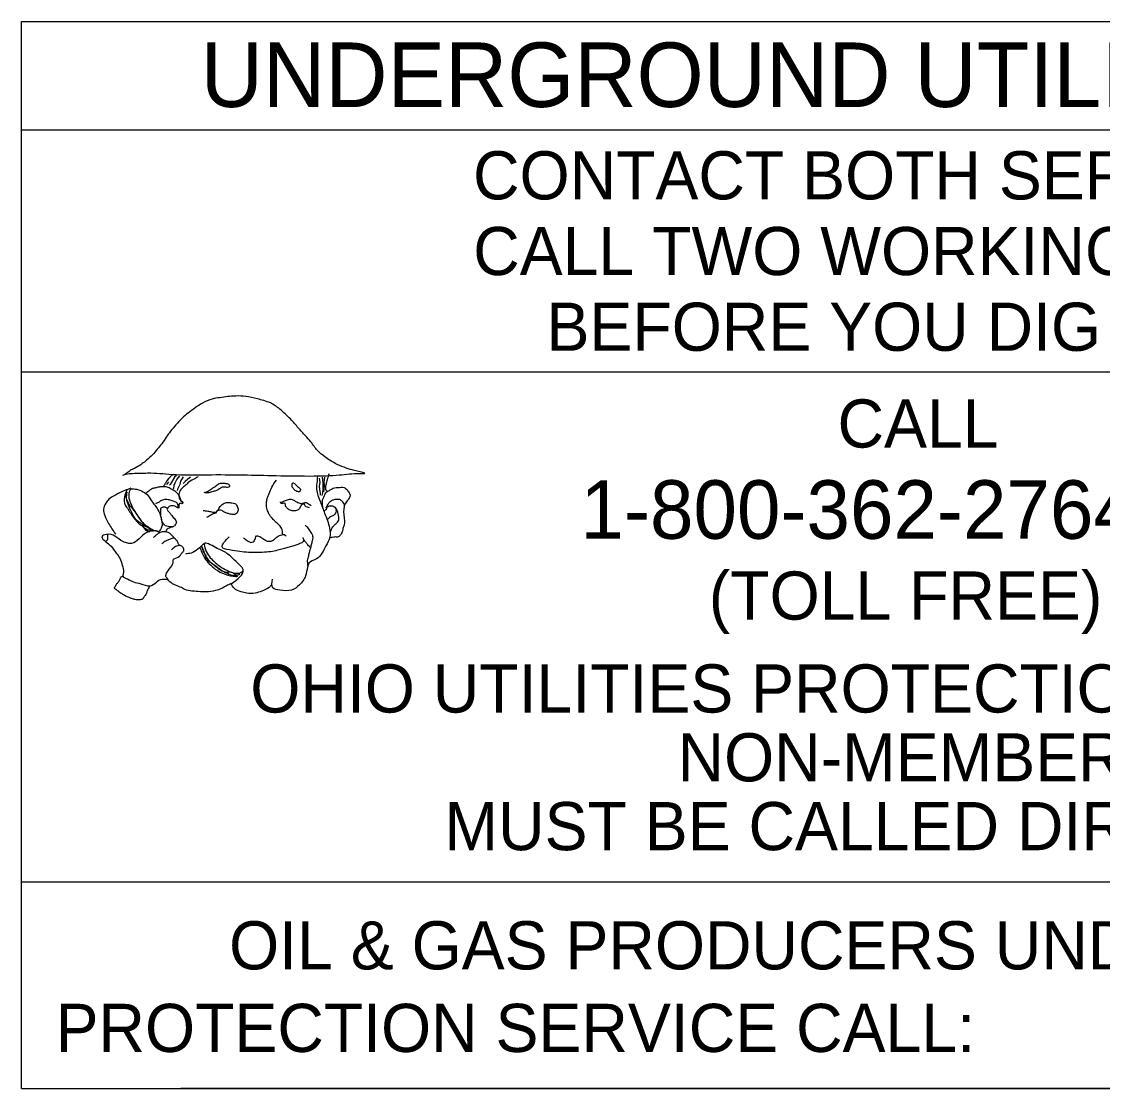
# Model space of a CAD drawing. Extents: x 0.4 to 34.4, y -2.1 to 19.9.
# Drawn here: x 3.425 to 6.568, y 0.086 to 3.186 of the extents above; entities that cross this region are included whole.
import ezdxf

# ---------------------------------------------------------------- set-up
doc = ezdxf.new("R2010")
doc.units = 0
doc.layers.add('SH_Data', color=7, linetype='Continuous')

msp = doc.modelspace()

# ---------------------------------------------------------------- linework, layer by layer
at = {"layer": 'SH_Data'}
for p, q in [((3.4251, 3.186), (8.6251, 3.186)), ((3.4251, 0.086), (3.4251, 3.186)), ((8.6251, 2.8706), (3.4251, 2.8706)), ((3.4251, 2.1681), (8.6251, 2.1681)), ((3.8694, 1.8617), (3.8624, 1.8509)), ((3.8752, 1.8667), (3.8694, 1.8617)), ((3.8762, 1.8559), (3.8703, 1.845)), ((3.8841, 1.8656), (3.8762, 1.8559)), ((3.895, 1.8627), (3.8871, 1.8509)), ((3.9087, 1.8559), (3.9008, 1.85)), ((3.9166, 1.8617), (3.9087, 1.8559)), ((4.2903, 1.8597), (4.2923, 1.8469)), ((4.2991, 1.8617), (4.3011, 1.846)), ((4.3061, 1.8617), (4.3041, 1.848)), ((3.8526, 1.8489), (3.8466, 1.8411)), ((3.8466, 1.8411), (3.8466, 1.8411)), ((3.8566, 1.8411), (3.8555, 1.8391)), ((3.8624, 1.8509), (3.8566, 1.8411)), ((3.8674, 1.8381), (3.8663, 1.8292)), ((3.8663, 1.8292), (3.8674, 1.8283)), ((3.8703, 1.845), (3.8674, 1.8381)), ((3.8782, 1.8272), (3.8771, 1.8233)), ((3.8811, 1.8331), (3.8782, 1.8272)), ((3.8851, 1.8411), (3.8811, 1.8331)), ((3.8871, 1.8509), (3.8851, 1.8411)), ((3.9008, 1.85), (3.895, 1.844)), ((4.2923, 1.8469), (4.2903, 1.8361)), ((4.2903, 1.8361), (4.2912, 1.8272)), ((4.2912, 1.8272), (4.2932, 1.8144)), ((4.3011, 1.8263), (4.3002, 1.8164)), ((4.3011, 1.846), (4.3011, 1.8351)), ((4.3011, 1.8351), (4.3011, 1.8263)), ((4.3041, 1.8263), (4.3031, 1.8193)), ((4.3041, 1.848), (4.3051, 1.8391)), ((4.3051, 1.8391), (4.3041, 1.8263)), ((4.2932, 1.8144), (4.2932, 1.8096)), ((4.3002, 1.8164), (4.2982, 1.8085)), ((3.4251, 0.686), (8.6251, 0.686)), ((3.4251, 0.086), (8.6251, 0.086)), ((3.8882, 0.086), (8.1621, 0.086)), ((8.1621, 0.086), (3.8882, 0.086))]:
    msp.add_line(p, q, dxfattribs=at)
for points in [[(4.42, 1.8727), (4.4223, 1.873), (4.4011, 1.8798), (4.3863, 1.8831), (4.3627, 1.8908), (4.3367, 1.9022), (4.3063, 1.9215), (4.2854, 1.9394), (4.2662, 1.9648), (4.2502, 1.9825), (4.2296, 2.0056), (4.2067, 2.0312), (4.1758, 2.0598), (4.1483, 2.0777), (4.1105, 2.0897), (4.0766, 2.0967), (4.0475, 2.098), (4.0011, 2.0931), (3.9795, 2.0891), (3.9513, 2.0776), (3.9295, 2.0635), (3.9095, 2.0484), (3.8916, 2.0335), (3.8736, 2.0144), (3.8579, 1.9954), (3.8457, 1.9783), (3.8324, 1.9594), (3.8196, 1.9435), (3.8059, 1.9271), (3.7881, 1.9112), (3.7758, 1.9014), (3.7583, 1.8902), (3.748, 1.8852), (3.7466, 1.8846), (3.7353, 1.8771), (3.7309, 1.8743), (3.7251, 1.8698)], [(3.7192, 1.868), (3.7251, 1.8698), (3.7416, 1.8729), (3.7659, 1.8733), (3.7916, 1.8743), (3.862, 1.8702), (3.9648, 1.8693), (4.0696, 1.8688), (4.165, 1.8668), (4.2755, 1.8656), (4.3486, 1.8686), (4.4075, 1.8731), (4.42, 1.8727)], [(3.8665, 1.8708), (3.8646, 1.8691), (3.8621, 1.8676), (3.858, 1.864), (3.8526, 1.8579), (3.8486, 1.8522), (3.8451, 1.8481), (3.8432, 1.8452), (3.8392, 1.8381), (3.8386, 1.8368), (3.8379, 1.8356), (3.8291, 1.8338), (3.825, 1.8335), (3.8166, 1.8316), (3.8078, 1.8296), (3.803, 1.8277), (3.7957, 1.8226), (3.7917, 1.8198), (3.7862, 1.8151)], [(3.9386, 1.8639), (3.9288, 1.8577), (3.9113, 1.8476), (3.9011, 1.8379), (3.8906, 1.8292), (3.8831, 1.816), (3.8825, 1.8079), (3.8874, 1.7956), (3.8937, 1.7877), (3.8912, 1.785), (3.8846, 1.7859), (3.8821, 1.778), (3.8819, 1.7726), (3.8704, 1.7783), (3.8641, 1.7789), (3.8541, 1.7771), (3.8488, 1.7683), (3.8541, 1.7606), (3.8604, 1.753), (3.8683, 1.7426), (3.8755, 1.7306), (3.8698, 1.7208)], [(4.2851, 1.8639), (4.2841, 1.851), (4.2827, 1.8276), (4.2938, 1.7897), (4.3061, 1.7576), (4.3204, 1.7138), (4.3211, 1.6876), (4.3098, 1.6622), (4.2824, 1.6246), (4.2604, 1.6118), (4.2562, 1.6002), (4.2507, 1.5756), (4.233, 1.5491), (4.2101, 1.534), (4.1758, 1.5342), (4.1558, 1.5405), (4.1548, 1.5656)], [(4.3191, 1.871), (4.3188, 1.8705), (4.3163, 1.8646), (4.3161, 1.8629), (4.3132, 1.8547), (4.3117, 1.848), (4.3104, 1.8415), (4.3083, 1.8319), (4.3084, 1.8291), (4.3091, 1.8256), (4.3115, 1.8231), (4.3129, 1.8204)], [(3.7426, 1.8301), (3.7075, 1.8152), (3.6944, 1.8081), (3.6791, 1.7983), (3.6696, 1.7862), (3.6632, 1.769), (3.6669, 1.7506), (3.6782, 1.7279), (3.6978, 1.6962)], [(3.7305, 1.8242), (3.7242, 1.8047), (3.7261, 1.7808), (3.7302, 1.7751), (3.7391, 1.7616), (3.7482, 1.7483), (3.7595, 1.7344), (3.7699, 1.7247), (3.7792, 1.7176), (3.7856, 1.7086), (3.797, 1.7035)], [(3.7312, 1.8252), (3.7287, 1.8186), (3.7278, 1.8104), (3.7282, 1.8047), (3.7313, 1.7963), (3.7362, 1.785), (3.7446, 1.7739), (3.7573, 1.7572), (3.7648, 1.7462), (3.7731, 1.7355), (3.7825, 1.7252), (3.7948, 1.7146), (3.7758, 1.7225), (3.789, 1.7109), (3.8004, 1.7083), (3.7646, 1.7326), (3.7486, 1.7534), (3.7409, 1.7692), (3.7345, 1.7833), (3.7305, 1.8005), (3.7317, 1.8183)], [(3.7426, 1.8277), (3.7394, 1.823), (3.7366, 1.8064), (3.7415, 1.7872), (3.7546, 1.7621), (3.7663, 1.7446), (3.7813, 1.7258), (3.7917, 1.7185), (3.8021, 1.7116), (3.8155, 1.7062), (3.8255, 1.7031)], [(3.7441, 1.8286), (3.76, 1.8268), (3.7781, 1.82), (3.793, 1.8081), (3.8054, 1.7891), (3.8145, 1.7777), (3.8266, 1.7563), (3.8323, 1.7381), (3.8323, 1.7168), (3.8244, 1.7044)], [(3.8927, 1.7881), (3.8911, 1.7906), (3.8878, 1.7971), (3.8842, 1.8067), (3.8776, 1.8158), (3.8705, 1.8217), (3.8604, 1.8275), (3.8482, 1.8334), (3.835, 1.8343)], [(3.9545, 1.819), (3.9611, 1.8172), (3.9732, 1.8186), (3.9857, 1.8221), (3.9948, 1.8255), (4.0058, 1.8322), (4.0131, 1.8344), (4.0234, 1.8333), (4.0307, 1.8355), (4.0277, 1.8411), (4.0203, 1.8431), (4.0096, 1.8438), (4.0027, 1.8435), (3.9911, 1.8365), (3.9837, 1.8318), (3.9709, 1.8231), (3.9655, 1.8196), (3.9571, 1.8171)], [(4.1852, 1.6954), (4.1841, 1.6973), (4.1841, 1.7016), (4.1836, 1.7052), (4.1805, 1.7143), (4.1727, 1.7239), (4.1633, 1.7326), (4.157, 1.7392), (4.1465, 1.7514), (4.1416, 1.761), (4.1376, 1.7762), (4.1374, 1.7909), (4.1395, 1.8016), (4.1452, 1.8148), (4.1526, 1.8331), (4.1663, 1.8533)], [(4.2132, 1.8437), (4.2111, 1.8423), (4.2107, 1.8396), (4.2107, 1.8352), (4.213, 1.8319), (4.2191, 1.8248), (4.2253, 1.8219), (4.2331, 1.8202), (4.2363, 1.8239), (4.2366, 1.8264), (4.2333, 1.8304), (4.2277, 1.8346), (4.2211, 1.8412), (4.2132, 1.8451)], [(4.3011, 1.7727), (4.3011, 1.7746), (4.3003, 1.7793), (4.2998, 1.7863), (4.2994, 1.7914), (4.3019, 1.8004), (4.3051, 1.8071), (4.3082, 1.8142), (4.3116, 1.8184), (4.3203, 1.8237), (4.3276, 1.8287), (4.3352, 1.8312), (4.3448, 1.8321), (4.354, 1.8327), (4.3625, 1.8319), (4.3673, 1.8291), (4.3725, 1.8242), (4.3755, 1.8194), (4.3794, 1.813), (4.3795, 1.8059), (4.377, 1.8), (4.3733, 1.7952), (4.3694, 1.7906), (4.3661, 1.7848), (4.364, 1.7804), (4.3626, 1.7744), (4.3616, 1.7673), (4.3613, 1.7592), (4.3621, 1.7508), (4.3634, 1.7414), (4.364, 1.7326), (4.3633, 1.7248), (4.3601, 1.7158), (4.3591, 1.7101), (4.3574, 1.7029), (4.3545, 1.6979), (4.3516, 1.6933), (4.3495, 1.6905), (4.3436, 1.688), (4.3374, 1.6883), (4.3326, 1.6876), (4.3241, 1.6872), (4.3211, 1.6871)], [(3.8807, 1.7756), (3.8799, 1.7796), (3.8754, 1.7884), (3.8661, 1.7921), (3.8542, 1.7959), (3.8406, 1.7968), (3.829, 1.7931), (3.8246, 1.7896), (3.8166, 1.786), (3.8151, 1.7851)], [(4.1769, 1.7879), (4.1834, 1.7909), (4.1921, 1.7946), (4.2036, 1.7981), (4.2142, 1.7967), (4.2228, 1.7915), (4.2284, 1.7887), (4.2391, 1.7858), (4.2523, 1.7888), (4.2567, 1.7863), (4.2623, 1.7831), (4.2667, 1.7801)], [(4.3103, 1.7733), (4.3117, 1.7752), (4.3136, 1.7786), (4.3165, 1.7842), (4.3196, 1.7888), (4.3248, 1.7933), (4.3284, 1.7955), (4.3321, 1.7963), (4.3361, 1.798), (4.3409, 1.7985), (4.3471, 1.7981), (4.3512, 1.7973), (4.3541, 1.7947), (4.3579, 1.7916), (4.3609, 1.786), (4.3625, 1.7843), (4.3628, 1.7823), (4.3632, 1.7796)], [(3.8411, 1.7218), (3.8376, 1.7269), (3.8336, 1.7323), (3.8319, 1.7411), (3.8296, 1.7489), (3.8295, 1.7546), (3.8296, 1.7659), (3.8325, 1.7743), (3.8369, 1.7756), (3.8413, 1.7756), (3.845, 1.7742), (3.8491, 1.7719), (3.8502, 1.77)], [(3.964, 1.7456), (3.9673, 1.7476), (3.9738, 1.7515), (3.98, 1.7556), (3.9874, 1.758), (3.9913, 1.759), (3.9903, 1.759), (3.9781, 1.7605), (3.9663, 1.7626), (3.9534, 1.7648)], [(3.9881, 1.758), (3.9967, 1.7675), (4.0007, 1.7742), (4.0112, 1.7846), (4.0241, 1.789), (4.0366, 1.7872), (4.0451, 1.7861), (4.0515, 1.7779), (4.0546, 1.766), (4.0532, 1.7612), (4.0496, 1.7562), (4.0437, 1.7539), (4.0308, 1.7551), (4.022, 1.7575), (4.0153, 1.7602), (4.0071, 1.7656)], [(4.0056, 1.766), (3.9983, 1.7663), (3.9969, 1.7655), (3.9932, 1.7621)], [(4.1828, 1.7856), (4.1787, 1.7871), (4.1783, 1.7901)], [(4.2479, 1.7881), (4.2436, 1.7841), (4.2391, 1.7808), (4.2359, 1.7768), (4.2327, 1.7706), (4.2295, 1.7672), (4.2242, 1.7654), (4.2181, 1.7642), (4.2062, 1.7663), (4.2, 1.7688), (4.1962, 1.7729), (4.1924, 1.7805), (4.1916, 1.7858), (4.1876, 1.7864), (4.1824, 1.7851)], [(4.2446, 1.7877), (4.2487, 1.7796), (4.2554, 1.7756), (4.2611, 1.7739)], [(4.3053, 1.7629), (4.3065, 1.7651), (4.3111, 1.7685), (4.3129, 1.7736), (4.3161, 1.7772), (4.3238, 1.7791), (4.3298, 1.7786), (4.3357, 1.7746), (4.3399, 1.7694), (4.3402, 1.7689), (4.3399, 1.7646), (4.3388, 1.76), (4.3361, 1.7548), (4.332, 1.7509), (4.3273, 1.7484), (4.3229, 1.7465), (4.3188, 1.7429), (4.3149, 1.7389)], [(4.3242, 1.7047), (4.3259, 1.7115), (4.3278, 1.7151), (4.3321, 1.72), (4.335, 1.7236), (4.3394, 1.7272), (4.3437, 1.7317), (4.347, 1.7371), (4.3475, 1.7469), (4.3452, 1.7565), (4.3428, 1.765), (4.3387, 1.7669)], [(3.824, 1.7033), (3.8162, 1.7059), (3.8066, 1.7056), (3.7871, 1.7005), (3.745, 1.6696), (3.7342, 1.6701), (3.7199, 1.6748), (3.6965, 1.6908), (3.6717, 1.6958), (3.6586, 1.689), (3.6687, 1.6755), (3.6855, 1.6613), (3.6998, 1.6417), (3.7106, 1.6265), (3.7176, 1.6064), (3.7212, 1.5852), (3.7199, 1.5748), (3.7332, 1.5663), (3.75, 1.5581), (3.7713, 1.5526), (3.7976, 1.5462), (3.817, 1.5571), (3.8341, 1.566), (3.8503, 1.5665), (3.8446, 1.5733), (3.8446, 1.5764), (3.8586, 1.6006), (3.8657, 1.6183), (3.8653, 1.62), (3.8806, 1.6297), (3.8916, 1.6426), (3.8966, 1.6485), (3.8946, 1.6579), (3.8861, 1.6633), (3.8721, 1.6602), (3.8612, 1.651)], [(3.8688, 1.6847), (3.8673, 1.6876), (3.8616, 1.6933), (3.855, 1.6997), (3.8465, 1.7023), (3.8376, 1.7033), (3.8306, 1.7019), (3.8219, 1.6983), (3.8146, 1.6923), (3.8084, 1.6865)], [(3.8691, 1.72), (3.8669, 1.7189), (3.8591, 1.7181), (3.8513, 1.7187), (3.8429, 1.7204)], [(3.868, 1.7188), (3.8624, 1.7173), (3.8582, 1.7162), (3.8541, 1.7143), (3.8488, 1.7113), (3.8466, 1.7094), (3.8455, 1.7076), (3.844, 1.7022)], [(4.2557, 1.6051), (4.2569, 1.6085), (4.2566, 1.6158), (4.2591, 1.631), (4.2621, 1.6429), (4.2667, 1.6606), (4.2695, 1.6726), (4.2723, 1.6831), (4.2721, 1.6901), (4.2711, 1.695), (4.2671, 1.7017), (4.2594, 1.713), (4.2492, 1.7226)], [(3.6683, 1.676), (3.6746, 1.6796), (3.6762, 1.6869), (3.6754, 1.6955)], [(3.8846, 1.6633), (3.8816, 1.6676), (3.8781, 1.6751), (3.8733, 1.6811), (3.8688, 1.6847), (3.8644, 1.6847), (3.8549, 1.6812), (3.845, 1.6767), (3.8333, 1.6686)], [(3.9552, 1.6696), (3.9177, 1.6414), (3.9023, 1.6392)], [(4.0341, 1.5521), (4.069, 1.5929), (4.0476, 1.6179), (4.0219, 1.6408), (3.9888, 1.6579), (3.9566, 1.6685), (3.9595, 1.6518), (3.984, 1.6176), (4.0233, 1.5909), (4.0667, 1.5884), (4.0682, 1.5901)], [(4.2646, 1.6569), (4.2623, 1.6602), (4.2571, 1.6651), (4.2511, 1.6733), (4.2484, 1.6764), (4.2462, 1.679), (4.2448, 1.6771), (4.2401, 1.6717), (4.228, 1.6669), (4.2162, 1.6626), (4.2031, 1.6584), (4.1891, 1.6551), (4.1737, 1.6509), (4.155, 1.6465), (4.1316, 1.6438), (4.104, 1.6431), (4.0851, 1.6433), (4.0596, 1.6459), (4.0295, 1.6506), (4.0079, 1.6601), (4.0126, 1.671), (4.0286, 1.6892)], [(4.0705, 1.6854), (4.0727, 1.6842), (4.0783, 1.6801), (4.0842, 1.676), (4.0913, 1.6726), (4.0986, 1.6744), (4.1027, 1.6787), (4.1048, 1.6848), (4.108, 1.6913), (4.1138, 1.691), (4.1265, 1.6841), (4.1376, 1.6773), (4.1469, 1.6759), (4.1607, 1.6821), (4.1684, 1.6887), (4.182, 1.6946), (4.189, 1.6951), (4.1941, 1.6919)], [(4.2459, 1.6793), (4.2459, 1.6813), (4.244, 1.6843), (4.244, 1.6872)], [(3.9428, 1.6584), (3.9569, 1.6281), (3.9883, 1.5951), (4.0479, 1.5739), (4.0536, 1.574)], [(3.9476, 1.6612), (3.9536, 1.6493), (3.9662, 1.6214), (3.9852, 1.6075), (4.0023, 1.5944), (4.0241, 1.5827), (4.0437, 1.5764), (4.0577, 1.5794)], [(3.9495, 1.6581), (3.9533, 1.6456), (3.9571, 1.6409), (3.9612, 1.633), (3.9658, 1.6247), (3.9751, 1.614), (3.9852, 1.6063), (3.9994, 1.5952), (4.0098, 1.589), (4.023, 1.5861), (4.0378, 1.5855), (4.0471, 1.5787), (4.0574, 1.5794), (4.0592, 1.5804)], [(3.7976, 1.5466), (3.7957, 1.5426), (3.7921, 1.5358), (3.7892, 1.5289), (3.7863, 1.5215), (3.7828, 1.5161), (3.7799, 1.5121), (3.7765, 1.5076), (3.7725, 1.5062), (3.7626, 1.5056), (3.7542, 1.5067), (3.7459, 1.5092), (3.7375, 1.5121), (3.7316, 1.5141), (3.7261, 1.5171), (3.7198, 1.5215), (3.7148, 1.5244), (3.7094, 1.5284), (3.7065, 1.5304), (3.7011, 1.5343), (3.698, 1.5368), (3.6946, 1.5392), (3.6966, 1.5431), (3.7011, 1.5511), (3.7065, 1.5576), (3.7109, 1.5644), (3.7148, 1.5729), (3.7187, 1.5747)], [(4.0341, 1.5533), (4.0305, 1.5514), (4.0174, 1.5446), (4.0061, 1.5383), (3.9888, 1.5327), (3.9616, 1.5286), (3.9451, 1.5293), (3.9204, 1.5311), (3.8996, 1.536), (3.8863, 1.5429), (3.8686, 1.5502), (3.8596, 1.5555), (3.8481, 1.5671)], [(4.1516, 1.5496), (4.1445, 1.5417), (4.1232, 1.5311), (4.1038, 1.5252), (4.0795, 1.5251), (4.0632, 1.5292), (4.0432, 1.5394), (4.0346, 1.5525)]]:
    msp.add_spline(points, degree=3, dxfattribs=at)

# ---------------------------------------------------------------- texts
for s, height, p in [('UNDERGROUND UTILITIES', 0.1875, (3.9457, 2.9379)), ('CONTACT BOTH SERVICES', 0.14, (4.7377, 2.6693)), ('CALL TWO WORKING DAYS', 0.14, (4.7382, 2.4493)), ('BEFORE YOU DIG', 0.14, (4.9514, 2.2293)), ('CALL', 0.14, (5.7975, 1.9481)), ('1-800-362-2764', 0.17, (5.0501, 1.6831)), ('(TOLL FREE)', 0.14, (5.4233, 1.4481)), ('OHIO UTILITIES PROTECTION SERVICE', 0.14, (4.0901, 1.1781)), ('NON-MEMBERS', 0.14, (5.3324, 0.9781)), ('MUST BE CALLED DIRECTLY', 0.14, (4.6545, 0.7781)), ('OIL & GAS PRODUCERS UNDERGROUND', 0.14, (4.0284, 0.4317)), ('PROTECTION SERVICE CALL:', 0.14, (3.5238, 0.1917))]:
    msp.add_text(s, height=height, dxfattribs=at).set_placement(p)

doc.saveas('drawing.dxf')
